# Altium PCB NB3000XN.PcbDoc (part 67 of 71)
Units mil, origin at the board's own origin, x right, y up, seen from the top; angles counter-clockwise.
Board outline 9527.56 x 6929.77 mil, 6 copper layers (Top Layer, GND+SHIELD, MidLayer1, MidLayer2, P2 - 3V3+5V0, Bottom Layer), stack 62.375 mil thick; 832 components, 1027 nets, 4655 pads, 4981 vias.
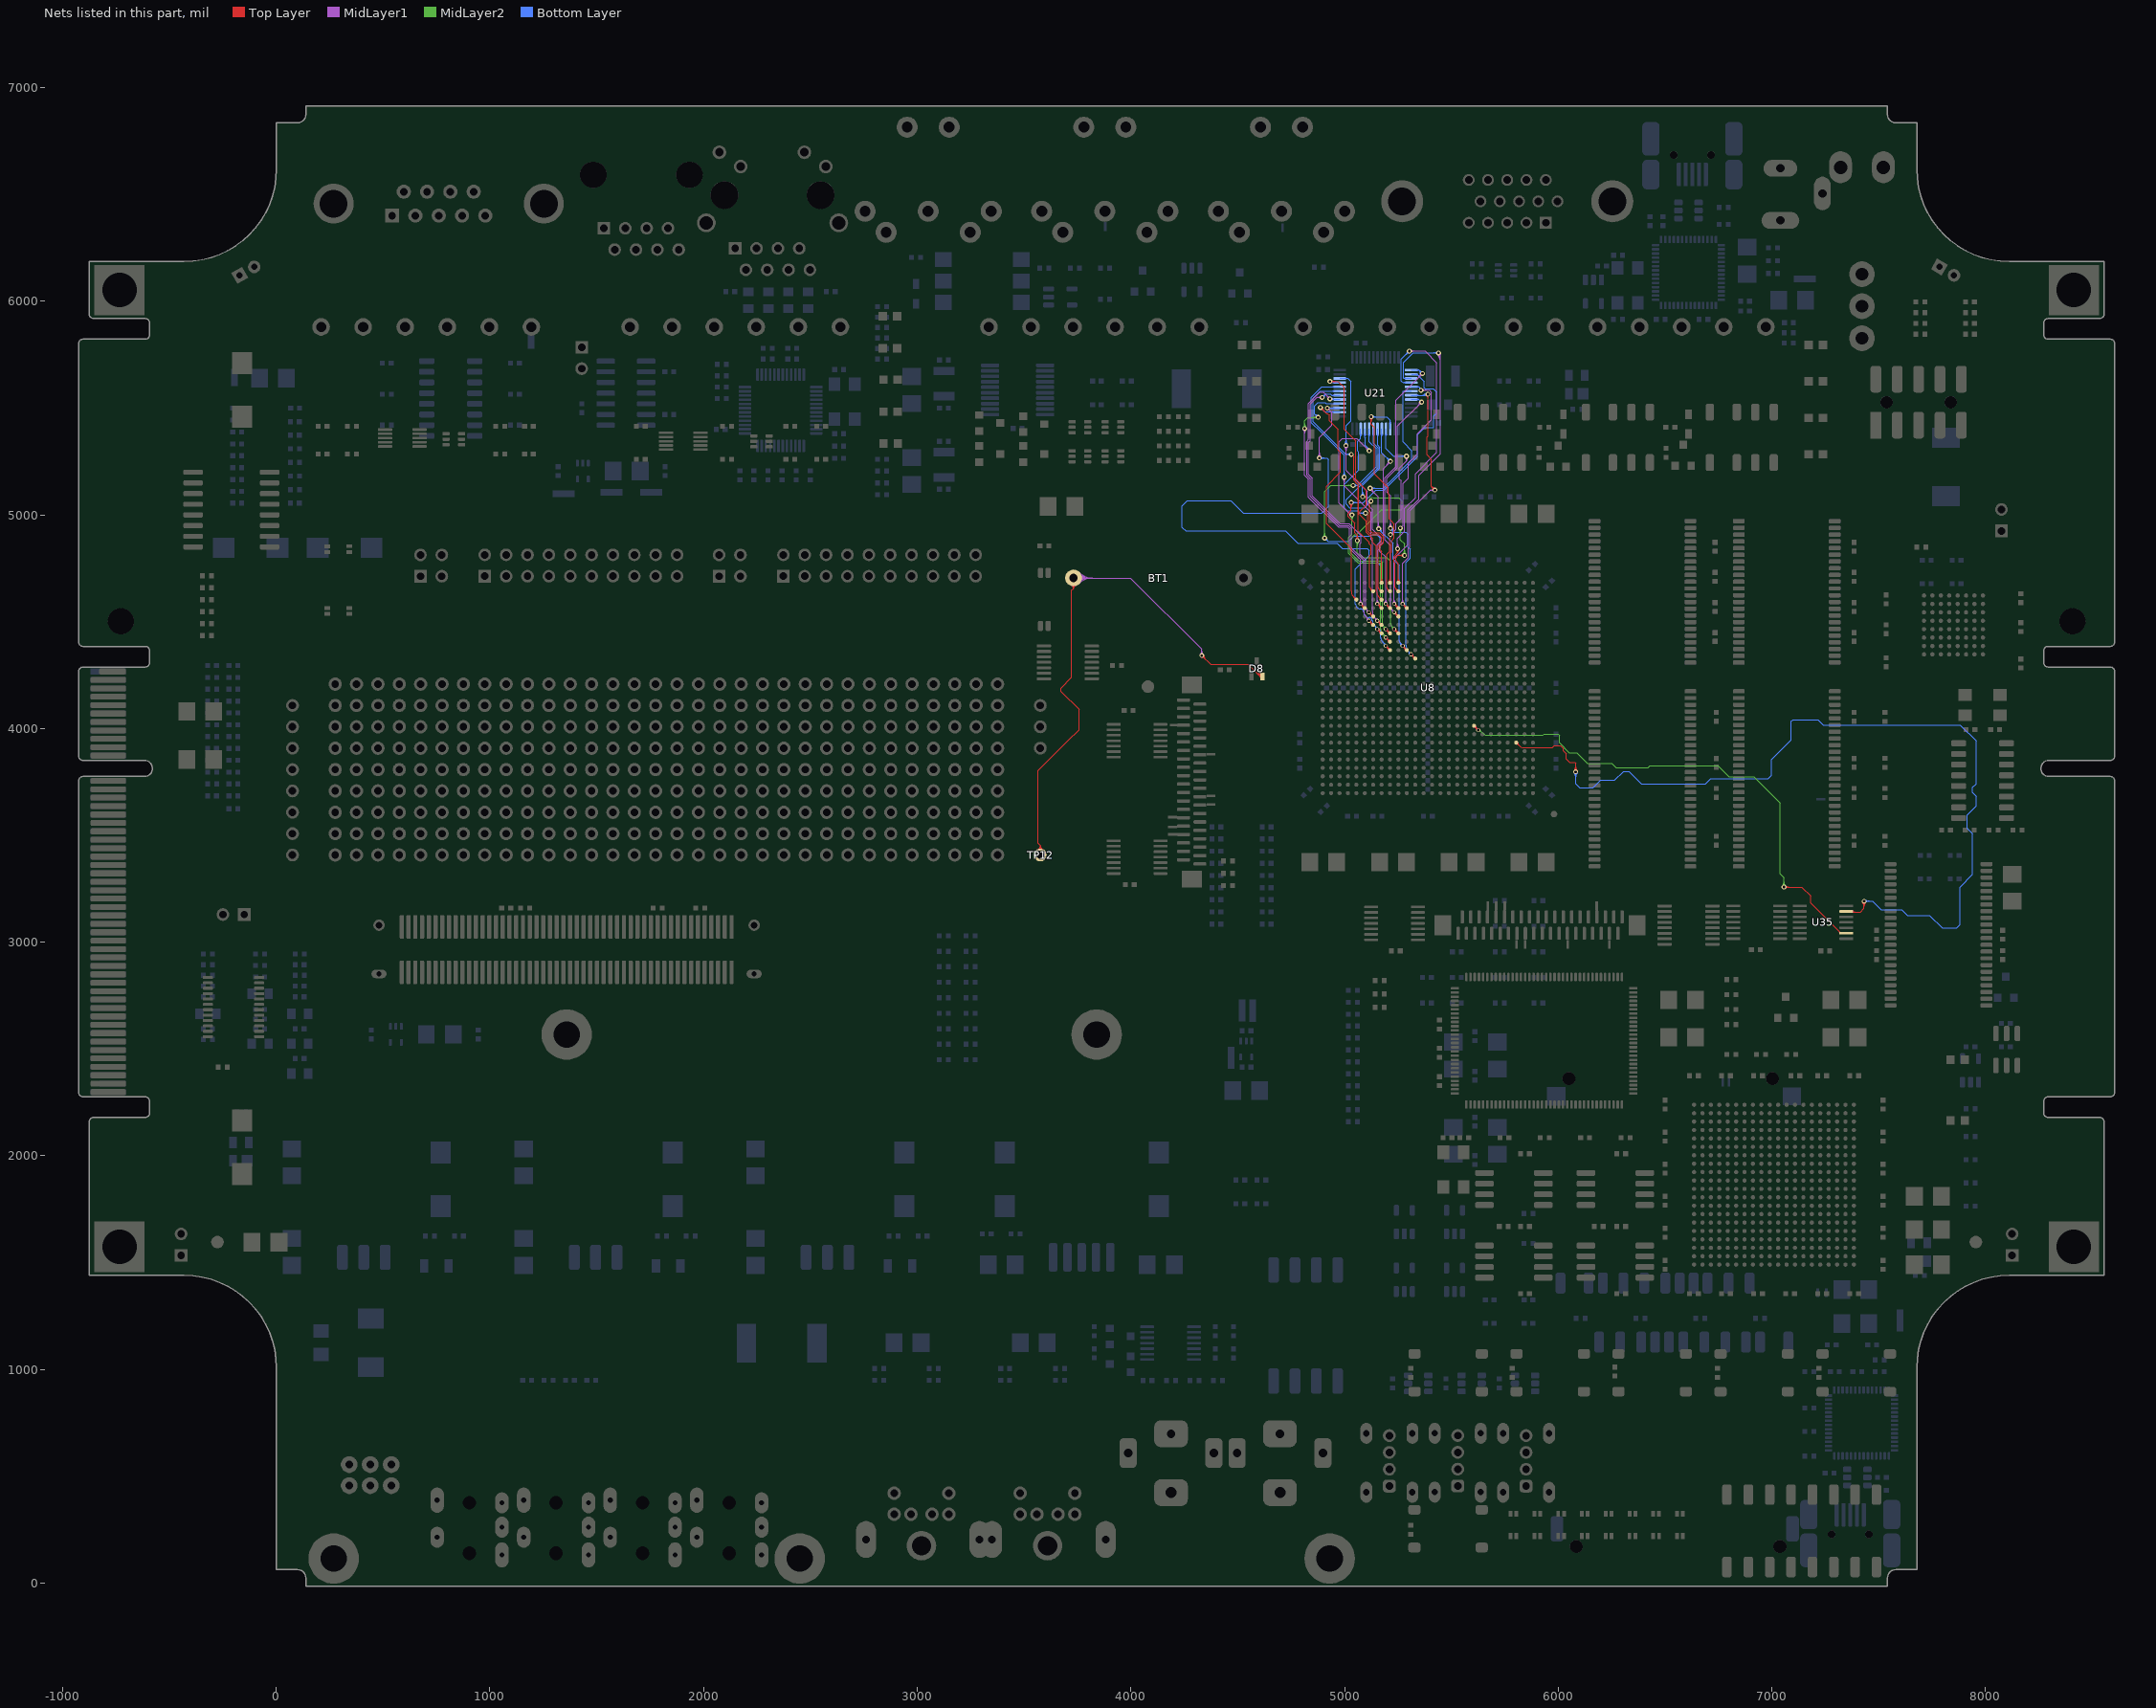
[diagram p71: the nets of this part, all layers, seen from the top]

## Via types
v1: diameter 23, hole 11.81, Top Layer to Bottom Layer, 3672 vias
v2: diameter 26, hole 11.81, Top Layer to Bottom Layer, 461 vias
v3: diameter 19, hole 11.81, Top Layer to Bottom Layer, tented both sides, 396 vias
v4: diameter 23.62, hole 11.81, Top Layer to Bottom Layer, 288 vias
v5: diameter 20, hole 11.81, Top Layer to Bottom Layer, 91 vias
v6: diameter 23, hole 11.81, Top Layer to Bottom Layer, tented both sides, 50 vias
v7: diameter 31, hole 11.81, Top Layer to Bottom Layer, 15 vias
v8: diameter 27.56, hole 11.81, Top Layer to Bottom Layer, tented both sides, 4 vias
v9: diameter 29, hole 11.81, Top Layer to Bottom Layer, 3 vias
v10: diameter 21, hole 11.81, Top Layer to Bottom Layer, 1 vias

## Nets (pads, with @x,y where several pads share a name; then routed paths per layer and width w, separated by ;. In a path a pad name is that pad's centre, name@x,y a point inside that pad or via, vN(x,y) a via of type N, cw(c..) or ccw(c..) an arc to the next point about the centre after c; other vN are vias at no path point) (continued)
USER_LEDS.LED7.GREEN: U8.Y24 U35.13 | length 4556.9
  Top Layer w4: v1@6075.14,3804.09 ccw(c6058.92,3820.31) 6081.86,3820.31 ccw(c6104.79,3820.31) v1@6088.57,3804.09 ; v1@6077.97,3801.26 ccw(c6068.58,3810.65) 6081.86,3810.65 ccw(c6095.14,3810.65) v1@6085.75,3801.26 ; v1(6081.86,3797.37) 6081.86,3838.14 6078.79,3841.21 6054.63,3841.21 6037.5,3858.34 6037.5,3882.73 6024.02,3896.2 6024.02,3907.29 6012.16,3919.15 5981.46,3919.15 5972.54,3910.23 5920,3910.23 5910,3910.23 5843.27,3910.23 ; U35.13@7348.5,3141.71 7415.19,3141.71 7431.86,3158.37 v1(7431.86,3191.71) ; U35.13@7374.98,3144.41 ccw(c7381.51,3150.93) 7381.51,3141.71 ; U35.13@7377.81,3147.24 ccw(c7391.16,3160.59) 7391.16,3141.71 ; v1@7425.14,3184.99 cw(c7408.92,3168.77) 7431.86,3168.77 cw(c7454.79,3168.77) v1@7438.57,3184.99 ; v1@7427.97,3187.82 cw(c7418.58,3178.43) 7431.86,3178.43 cw(c7445.14,3178.43) v1@7435.75,3187.82 ; 5815.92,3921.56 ccw(c5843.27,3948.91) 5843.27,3910.23 ; 5815.92,3921.56 ccw(c5843.27,3948.91) 5843.27,3910.23 ; 5815.92,3921.56 ccw(c5803.39,3909.03) 5803.39,3926.75 cw(c5803.39,3909.03) 5815.92,3921.56 ; 5815.92,3921.56 cw(c5828.45,3934.09) 5810.73,3934.09 ccw(c5828.45,3934.09) 5815.92,3921.56
  Bottom Layer w4: v1@6075.14,3790.66 cw(c6058.92,3774.44) 6081.86,3774.44 cw(c6104.79,3774.44) v1@6088.57,3790.66 ; v1@6077.97,3793.49 cw(c6068.58,3784.1) 6081.86,3784.1 cw(c6095.14,3784.1) v1@6085.75,3793.49 ; v1(6081.86,3797.37) 6081.86,3741.96 6099.78,3724.04 6164.19,3724.04 6198.52,3758.37 6265.19,3758.37 6306.86,3800.04 6331.86,3800.04 6390.19,3741.71 6690.19,3741.71 6715.19,3766.71 6983.19,3766.71 6998.52,3782.04 6998.52,3855.39 7090.19,3947.06 7090.19,4033.37 7098.52,4041.71 7215,4041.71 7240,4016.71 7306.86,4016.71 7345,4016.71 7881.86,4016.71 7956.86,3941.71 7956.86,3741.71 7940.19,3725.04 7940.19,3700.04 7956.86,3683.37 7956.86,3638.04 7915.19,3596.37 7915.19,3533.37 7940.19,3508.37 7940.19,3316.71 7881.86,3258.37 7881.86,3083.37 7865.19,3066.71 7797.02,3066.71 7738.73,3125 7633.69,3125 7607.23,3151.46 7510.79,3151.46 ; v1(7431.86,3191.71) 7470.54,3191.71 7510.79,3151.46 ; v1@7435.75,3187.82 cw(c7445.14,3178.43) 7445.14,3191.71 cw(c7445.14,3204.99) v1@7435.75,3195.6 ; v1@7438.57,3184.99 cw(c7454.79,3168.77) 7454.79,3191.71 cw(c7454.79,3214.64) v1@7438.57,3198.43 ; 7479.3,3182.95 7510.79,3151.46
USER_LEDS.LED7.RED: U8.V19 U35.9 | length 2687.9
  Top Layer w4: U8.V19@5606.54,4005.33 cw(c5606.54,3987.23) 5619.34,4000.03 cw(c5632.14,4012.83) U8.V19@5614.04,4012.83 ; U8.V19@5606.54,4005.49 cw(c5606.54,3987.77) 5619.07,4000.3 cw(c5631.6,4012.83) U8.V19@5613.88,4012.83 ; U8.V19@5606.54,4012.83 v3(5626.22,3993.15) ; v1(7056.86,3258.37) 7140.19,3258.37 7181.52,3217.04 7181.52,3183.71 7323.52,3041.71 7348.5,3041.71 U35.9@7348.5,3042.05 ; v1@7060.75,3254.49 cw(c7070.14,3245.1) 7070.14,3258.37 cw(c7070.14,3271.65) v1@7060.75,3262.26 ; v1@7063.57,3251.66 cw(c7079.79,3235.44) 7079.79,3258.37 cw(c7079.79,3281.31) v1@7063.57,3265.09 ; 7314.37,3050.86 cw(c7305.56,3042.05) U35.9@7318.02,3042.05 ; 7317.18,3048.06 ccw(c7322.02,3052.9) U35.9@7322.02,3046.05 ; 5613.42,4005.95 cw(c5600.61,3993.15) 5618.72,3993.15 ccw(c5600.61,3993.15) 5613.42,4005.95 ; 5613.42,4005.95 ccw(c5626.22,4018.76) 5626.22,4000.65 cw(c5626.22,4018.76) 5613.42,4005.95
  MidLayer2 w4: v3@5627.52,3985.76 cw(c5630.67,3967.93) 5641.05,3982.76 ; v3@5633.61,3994.45 ccw(c5651.44,3997.6) 5641.05,3982.76 ; v1@7050.14,3265.09 ccw(c7033.92,3281.31) 7056.86,3281.31 ccw(c7079.79,3281.31) v1@7063.57,3265.09 ; v1@7052.97,3262.26 ccw(c7043.58,3271.65) 7056.86,3271.65 ccw(c7070.14,3271.65) v1@7060.75,3262.26 ; 7055,3305 7039.86,3320.14 ; v1(7056.86,3258.37) 7056.86,3303.14 7039.86,3320.14 ; 5641.05,3982.76 5649.63,3975.68 ccw(c5665.85,3993.06) 5665.85,3969.29 5689.1,3969.29 5763.22,3969.29 5782.64,3969.29 5910,3969.29 5920,3969.29 5929.29,3969.29 5935,3975 6000,3975 6006,3969 6006,3933 6052,3887 6087.69,3887 6137.13,3837.56 6249.68,3837.56 6270.52,3816.71 6420.54,3816.71 6428.88,3825.04 6748.52,3825.04 6798.52,3775.04 6915.19,3775.04 7039.86,3650.37 7039.86,3320.14
VBATT: BT1.1 D8.2 TP12.1 | length 3668
  Top Layer w4: TP12.1@3564.05,3433.5 ccw(c3554.92,3452.64) 3576.12,3452.64 ; TP12.1@3565.78,3429.89 ccw(c3557.95,3446.29) 3576.12,3446.29 ccw(c3594.3,3446.29) TP12.1@3586.46,3429.89 ; TP12.1@3567.5,3426.28 ccw(c3560.97,3439.95) 3576.12,3439.95 ccw(c3591.27,3439.95) TP12.1@3584.74,3426.28 ; TP12.1@3576.12,3408.23 3576.12,3452.64 ; TP12.1@3588.19,3433.5 cw(c3597.33,3452.64) 3576.12,3452.64 ; BT1.1@3721.44,4669.07 cw(c3717.53,4655.42) 3731.73,4655.42 ; BT1.1@3722.54,4672.92 cw(c3719.05,4660.73) 3731.73,4660.73 cw(c3744.41,4660.73) BT1.1@3740.92,4672.92 ; BT1.1@3731.73,4705 3731.73,4655.42 ; BT1.1@3742.02,4669.07 ccw(c3745.93,4655.42) 3731.73,4655.42 ; v1@4331.86,4332.21 cw(c4331.86,4309.27) 4348.07,4325.49 cw(c4364.29,4341.71) v1@4341.36,4341.71 ; v1@4331.86,4336.21 cw(c4331.86,4322.93) 4341.25,4332.32 cw(c4350.64,4341.71) v1@4337.36,4341.71 ; v1(4331.86,4341.71) 4373.52,4300.04 4548.52,4300.04 4604,4244.57 D8.2@4615.59,4244.57 ; 4568.97,4279.59 ccw(c4615.59,4326.21) D8.2@4615.59,4260.28 ; 4575.8,4272.77 ccw(c4615.59,4312.56) D8.2@4615.59,4256.28 ; 4582.63,4265.94 ccw(c4615.59,4298.9) D8.2@4615.59,4252.28 ; 4589.46,4259.11 ccw(c4615.59,4285.24) D8.2@4615.59,4248.28 ; 4596.28,4252.28 ccw(c4615.59,4271.59) D8.2@4615.59,4244.28 ; 4603.11,4245.45 ccw(c4615.59,4257.93) D8.2@4615.59,4240.28 ; D8.2@4608.11,4241.73 ccw(c4604,4240.17) 4604,4244.57 ccw(c4604,4248.97) D8.2@4608.11,4247.4 ; 3576.12,3452.64 3565.19,3463.57 3565.19,3803.02 3705.04,3942.87 3757.19,3995.02 3757.19,4089.37 3673.52,4173.04 3673.52,4189.71 3723.52,4239.71 3723.52,4647.21 3731.73,4655.42
  MidLayer1 w4: BT1.1@3731.73,4705 3998.69,4705 4331.86,4371.83 v1(4331.86,4341.71) ; BT1.1@3744.01,4692.72 cw(c3773.67,4663.07) 3773.67,4705 cw(c3773.67,4746.94) BT1.1@3744.01,4717.28 ; BT1.1@3746.84,4689.89 cw(c3783.32,4653.41) 3783.32,4705 cw(c3783.32,4756.59) BT1.1@3746.84,4720.11 ; BT1.1@3749.67,4687.06 cw(c3792.98,4643.75) 3792.98,4705 cw(c3792.98,4766.25) BT1.1@3749.67,4722.94 ; BT1.1@3752.5,4684.23 cw(c3802.64,4634.09) 3802.64,4705 cw(c3802.64,4775.91) BT1.1@3752.5,4725.77 ; BT1.1@3755.33,4681.4 cw(c3812.29,4624.44) 3812.29,4705 cw(c3812.3,4785.56) BT1.1@3755.33,4728.6 ; BT1.1@3758.16,4678.58 cw(c3821.95,4614.78) 3821.95,4705 cw(c3821.95,4795.22) BT1.1@3758.16,4731.42 ; v1@4325.14,4348.43 ccw(c4308.92,4364.64) 4331.86,4364.64 ccw(c4354.79,4364.64) v1@4338.57,4348.43 ; v1@4327.97,4345.6 ccw(c4318.58,4354.99) 4331.86,4354.99 ccw(c4345.14,4354.99) v1@4335.75,4345.6
VGA.BLUE0: U8.K12 U21.8 | length 1731.7
  Top Layer w4: v3(5311.26,4347.48) U8.K12@5330.94,4327.8 ; U8.K12@5323.44,4327.8 ccw(c5305.34,4327.8) 5318.14,4340.6 ccw(c5330.94,4353.4) U8.K12@5330.94,4335.3 ; U8.K12@5323.6,4327.8 ccw(c5305.88,4327.8) 5318.41,4340.33 ccw(c5330.94,4352.86) U8.K12@5330.94,4335.14 ; 5324.06,4334.68 cw(c5336.87,4347.48) 5318.76,4347.48 ccw(c5336.87,4347.48) 5324.06,4334.68 ; 5324.06,4334.68 ccw(c5311.26,4321.87) 5311.26,4339.98 cw(c5311.26,4321.87) 5324.06,4334.68
  MidLayer1 w4: v1@5208.47,4944.09 ccw(c5192.26,4960.31) 5215.19,4960.31 ccw(c5238.13,4960.31) v1@5221.91,4944.09 ; v1@5211.3,4941.26 ccw(c5201.91,4950.65) 5215.19,4950.65 ccw(c5228.47,4950.65) v1@5219.08,4941.26 ; v1(5215.19,4937.37) 5215.19,5049.94 5215.19,5089.81 5198.19,5106.81 5198.19,5171.69 5248.52,5222.02 5248.52,5415.52 v1(5361,5528) ; v1@5351.5,5528 cw(c5328.56,5528) 5344.78,5511.78 cw(c5361,5495.56) v1@5361,5518.5 ; v1@5355.5,5528 cw(c5342.22,5528) 5351.61,5518.61 cw(c5361,5509.22) v1@5361,5522.5
  Bottom Layer w4: v1@5215.19,4927.87 cw(c5215.19,4904.94) 5231.41,4921.16 cw(c5247.63,4937.37) v1@5224.69,4937.37 ; v1@5215.19,4931.87 cw(c5215.19,4918.6) 5224.58,4927.99 cw(c5233.97,4937.37) v1@5220.69,4937.37 ; v1(5215.19,4937.37) 5232.56,4920 5287.52,4920 5297.52,4910 5297.52,4850.04 5306.86,4840.71 5306.86,4797.02 5287.4,4777.56 5287.4,4724.74 5287.4,4720 5287.4,4710 5287.4,4503.9 5287.4,4484.48 5287.4,4410.36 5287.4,4390.86 ccw(c5329.13,4390.86) 5299.62,4361.35 ; v3@5303.79,4348.13 ccw(c5285.75,4349.71) 5299.62,4361.35 ; v3@5311.91,4354.95 cw(c5313.49,4372.99) 5299.62,4361.35 ; U21.8@5312.32,5540.47 5346.09,5540.47 5358.56,5528 v1(5361,5528) ; U21.8@5338.68,5537.64 cw(c5345.51,5530.82) 5345.51,5540.47 cw(c5345.51,5550.13) U21.8@5338.68,5543.3
VGA.BLUE1: U8.D11 U21.7 | length 1561.1
  Top Layer w4: v3(5271.89,4583.7) U8.D11@5291.57,4564.02 ; U8.D11@5284.07,4564.02 ccw(c5265.97,4564.02) 5278.77,4576.82 ccw(c5291.57,4589.62) U8.D11@5291.57,4571.52 ; U8.D11@5284.23,4564.02 ccw(c5266.51,4564.02) 5279.04,4576.55 ccw(c5291.57,4589.08) U8.D11@5291.57,4571.36 ; v1(5390,5565) 5387.48,5565 5381.86,5559.37 5383.12,5558.12 5390.19,5551.04 5390.19,5370.04 5385.52,5365.37 5385.52,5281.37 5406.86,5260.04 5406.86,5133.37 v1(5423.52,5116.71) ; v1@5414.02,5116.71 ccw(c5391.09,5116.71) 5407.31,5132.93 ccw(c5423.52,5149.14) v1@5423.52,5126.21 ; v1@5418.02,5116.71 ccw(c5404.75,5116.71) 5414.14,5126.1 ccw(c5423.52,5135.49) v1@5423.52,5122.21 ; 5284.69,4570.9 cw(c5297.5,4583.7) 5279.39,4583.7 ccw(c5297.5,4583.7) 5284.69,4570.9 ; 5284.69,4570.9 ccw(c5271.89,4558.09) 5271.89,4576.2 cw(c5271.89,4558.09) 5284.69,4570.9
  MidLayer1 w4: v3@5266.59,4589 ccw(c5253.78,4601.81) 5271.89,4601.81 ccw(c5290,4601.81) v3@5277.19,4589 ; v3@5266.7,4588.89 ccw(c5254.16,4601.43) 5271.89,4601.43 ccw(c5289.62,4601.43) v3@5277.08,4588.89 ; v3(5271.89,4583.7) 5271.89,4661.38 5271.89,4710 5271.89,4720 5271.89,4773.37 5298.52,4800 5298.52,4843.02 5305.52,4850.02 5305.52,5020.37 5401.86,5116.71 ; v1@5416.54,5110.27 ccw(c5401.86,5096.75) 5401.86,5116.71 ; v1@5416.54,5123.14 cw(c5401.86,5136.66) 5401.86,5116.71 ; v1@5419.48,5112.98 ccw(c5410.98,5105.15) 5410.98,5116.71 ccw(c5410.98,5128.26) v1@5419.48,5120.43 ; v1(5423.52,5116.71) 5401.86,5116.71
  Bottom Layer w4: U21.7@5312.32,5560.16 5348.52,5560.16 5349.31,5559.37 5384.37,5559.37 v1(5390,5565) ; U21.7@5338.68,5557.33 cw(c5345.51,5550.5) 5345.51,5560.16 cw(c5345.51,5569.82) U21.7@5338.68,5562.99 ; 5353.48,5559.37 ccw(c5353.48,5601.52) v1@5383.28,5571.72 ; 5363.14,5559.37 ccw(c5363.14,5591.86) v1@5386.11,5568.89 ; 5372.8,5559.37 ccw(c5372.8,5582.2) v1@5388.94,5566.06
VGA.BLUE2: U8.J11 U21.6 | length 1834.4
  Top Layer w4: v3(5271.89,4386.85) U8.J11@5291.57,4367.17 ; U8.J11@5284.07,4367.17 ccw(c5265.97,4367.17) 5278.77,4379.97 ccw(c5291.57,4392.77) U8.J11@5291.57,4374.67 ; U8.J11@5284.23,4367.17 ccw(c5266.51,4367.17) 5279.04,4379.7 ccw(c5291.57,4392.23) U8.J11@5291.57,4374.51 ; 5284.69,4374.05 cw(c5297.5,4386.85) 5279.39,4386.85 ccw(c5297.5,4386.85) 5284.69,4374.05 ; 5284.69,4374.05 ccw(c5271.89,4361.24) 5271.89,4379.35 cw(c5271.89,4361.24) 5284.69,4374.05
  MidLayer1 w4: v1@5116.19,5125.04 v1@5116.23,5125 ; v1@5120,5115.5 cw(c5120,5101.66) 5129.78,5111.45 ; v1(5120,5125) v1@5116.23,5125 ; v1@5125.5,5125 ccw(c5147.88,5125) 5132.05,5109.18 ; v1@5129.5,5125 ccw(c5161.53,5125) 5138.88,5102.35 ; v1@5153.28,4941.72 ccw(c5144.65,4950.35) 5156.86,4950.35 ; 5156.86,4946.21 ccw(c5171.21,4946.21) v1@5161.06,4936.06 ; 5156.86,4955.87 ccw(c5180.87,4955.87) v1@5163.89,4938.89 ; 5156.86,4965.52 ccw(c5190.52,4965.52) v1@5166.72,4941.72 ; v1(5160,4935) 5158.9,4935 5156.86,4937.04 5156.86,5084.37 5118.12,5123.12 v1@5116.23,5125
  Bottom Layer w4: v1(5120,5125) 5116.23,5125 5116.19,5125.04 5181.88,5125.04 5315.19,5258.35 5315.19,5300.04 5273.52,5341.71 5273.52,5578.52 5274.84,5579.84 U21.6@5312.32,5579.84 ; v1@5123.89,5121.11 cw(c5133.38,5111.62) 5133.38,5125.04 ; v1@5123.89,5128.89 ccw(c5133.18,5138.18) 5133.18,5125.04 ; v1@5126.72,5118.28 cw(c5143.03,5101.97) 5143.03,5125.04 ; v1@5126.72,5131.72 ccw(c5142.84,5147.84) 5142.84,5125.04 ; v1@5160,4925.5 cw(c5160,4905.23) 5174.34,4919.56 ; v1(5160,4935) 5158.9,4935 5227.19,4866.71 5227.19,4792.81 5256.38,4763.62 5256.38,4757.96 5256.38,4720 5256.38,4710 5256.38,4503.9 5256.38,4410.36 ccw(c5270.43,4410.36) 5260.5,4400.43 ; v1@5165.5,4935 ccw(c5181.44,4935) 5170.17,4923.73 ; v1@5169.5,4935 ccw(c5195.1,4935) 5177,4916.9 ; v3@5264.42,4387.5 ccw(c5246.38,4389.08) 5260.25,4400.72 ccw(c5274.12,4412.36) v3@5272.54,4394.32 ; U21.6@5285.97,5577.01 ccw(c5279.14,5570.19) 5279.14,5579.84 ccw(c5279.14,5589.5) U21.6@5285.97,5582.67
VGA.BLUE3: U8.A10 U21.5 | length 1455.2
  Top Layer w4: U8.A10@5246.9,4687.43 ccw(c5234.1,4700.23) 5252.2,4700.23 ccw(c5270.31,4700.23) U8.A10@5257.51,4687.43 ; U8.A10@5252.2,4682.13 5252.2,4710 5252.2,4720 5252.2,4724.74 5252.21,4771.94 5240,4784.15 5240,4800 5250.37,4810.37 v1(5280.52,4810.37) ; v1@5273.81,4803.66 ccw(c5257.59,4787.44) 5257.59,4810.37 ccw(c5257.59,4833.31) v1@5273.81,4817.09 ; v1@5276.64,4806.49 ccw(c5267.25,4797.1) 5267.25,4810.37 ccw(c5267.25,4823.65) v1@5276.64,4814.26 ; 5252.2,4699.85 cw(c5234.48,4699.85) 5247.01,4687.32 ccw(c5234.48,4699.85) 5252.2,4699.85 ; 5252.2,4699.85 ccw(c5269.93,4699.85) 5257.4,4687.32 cw(c5269.93,4699.85) 5252.2,4699.85
  MidLayer1 w4: v1(5261.52,4938.37) 5273.52,4950.37 5273.52,5146.37 5298.52,5171.37 5298.52,5241.69 5309.11,5252.28 5342.19,5285.37 5342.19,5380.71 5407.5,5446.02 5407.5,5572.25 5396.37,5583.37 v1(5357.86,5583.37) ; v1@5361.75,5579.49 cw(c5371.14,5570.1) 5371.14,5583.37 cw(c5371.14,5596.65) v1@5361.75,5587.26 ; v1@5364.57,5576.66 cw(c5380.79,5560.44) 5380.79,5583.37 cw(c5380.79,5606.31) v1@5364.57,5590.09
  MidLayer2 w4: v1@5254.81,4931.66 cw(c5238.59,4915.44) 5261.52,4915.44 cw(c5284.46,4915.44) v1@5268.24,4931.66 ; v1@5257.64,4934.49 cw(c5248.25,4925.1) 5261.52,4925.1 cw(c5274.8,4925.1) v1@5265.41,4934.49 ; v1(5261.52,4938.37) 5261.52,4883.37 5280.52,4864.37 v1(5280.52,4810.37) ; v1@5273.81,4817.09 ccw(c5257.59,4833.31) 5280.52,4833.31 ccw(c5303.46,4833.31) v1@5287.24,4817.09 ; v1@5276.64,4814.26 ccw(c5267.25,4823.65) 5280.52,4823.65 ccw(c5293.8,4823.65) v1@5284.41,4814.26
  Bottom Layer w4: U21.5@5312.32,5599.53 5347.86,5599.53 5357.86,5589.53 v1(5357.86,5583.37) ; U21.5@5338.68,5596.7 cw(c5345.51,5589.87) 5345.51,5599.53 cw(c5345.51,5609.18) U21.5@5338.68,5602.36 ; 5349.45,5597.94 cw(c5340.38,5588.87) v1@5352.61,5585.03 ; 5352.14,5595.24 ccw(c5357.86,5600.96) v1@5357.86,5592.87
VGA.BLUE4: U8.B10 U21.4 | length 1775.1
  Top Layer w4: v1@5242.72,4833.85 cw(c5233.6,4822.04) 5248.52,4822.04 ; v1(5248.52,4841.37) 5248.52,4822.04 ; v1@5254.33,4833.85 ccw(c5263.45,4822.04) 5248.52,4822.04 ; 5236.7,4662.47 ccw(c5246.85,4662.47) 5239.67,4655.29 ; 5236.7,4662.47 ccw(c5246.85,4662.47) 5239.67,4655.29 ; 5236.7,4662.47 5236.7,4710 5236.7,4720 5236.7,4724.74 5236.7,4776.14 5232,4780.84 5232,4805.52 5248.52,4822.04 ; 5239.67,4655.29 ccw(c5252.2,4667.83) 5252.2,4650.1 cw(c5252.2,4667.83) 5239.67,4655.29 ; 5239.67,4655.29 cw(c5227.14,4642.76) 5244.86,4642.76 ccw(c5227.14,4642.76) 5239.67,4655.29
  MidLayer1 w4: v1@5241.81,4848.09 ccw(c5225.59,4864.31) 5248.52,4864.31 ccw(c5271.46,4864.31) v1@5255.24,4848.09 ; v1@5244.64,4845.26 ccw(c5235.25,4854.65) 5248.52,4854.65 ccw(c5261.8,4854.65) v1@5252.41,4845.26 ; v1(5248.52,4841.37) 5248.52,4890.37 5281.52,4923.37 5281.52,5030.32 5331.86,5080.65 5331.86,5191.71 5432.19,5292.04 5432.19,5711.69 ; v1(5303.52,5766.71) 5377.17,5766.71 5431.86,5712.02 ; v1@5307.41,5762.82 cw(c5316.8,5753.43) 5316.8,5766.71 cw(c5316.8,5779.99) v1@5307.41,5770.6 ; v1@5310.24,5759.99 cw(c5326.46,5743.77) 5326.46,5766.71 cw(c5326.46,5789.64) v1@5310.24,5773.43
  Bottom Layer w4: U21.4@5285.97,5616.38 ccw(c5279.14,5609.56) 5279.14,5619.21 ccw(c5279.14,5628.87) U21.4@5285.97,5622.04 ; v1@5294.02,5766.71 cw(c5271.09,5766.71) 5287.31,5750.49 cw(c5303.52,5734.27) v1@5303.52,5757.21 ; v1@5298.02,5766.71 cw(c5284.75,5766.71) 5294.14,5757.32 cw(c5303.52,5747.93) v1@5303.52,5761.21 ; v1(5303.52,5766.71) 5265.52,5728.71 5265.52,5627.21 5273.52,5619.21 U21.4@5312.32,5619.21
VGA.BLUE5: U8.D10 U21.3 | length 1972.9
  Top Layer w4: v3(5232.52,4583.7) U8.D10@5252.2,4564.02 ; U8.D10@5244.7,4564.02 ccw(c5226.6,4564.02) 5239.4,4576.82 ccw(c5252.2,4589.62) U8.D10@5252.2,4571.52 ; U8.D10@5244.86,4564.02 ccw(c5227.14,4564.02) 5239.67,4576.55 ccw(c5252.2,4589.08) U8.D10@5252.2,4571.36 ; 5245.32,4570.9 cw(c5258.13,4583.7) 5240.02,4583.7 ccw(c5258.13,4583.7) 5245.32,4570.9 ; 5245.32,4570.9 ccw(c5232.52,4558.09) 5232.52,4576.2 cw(c5232.52,4558.09) 5245.32,4570.9
  MidLayer1 w4: v3@5227.33,4588.89 ccw(c5214.79,4601.43) 5232.52,4601.43 ccw(c5250.25,4601.43) v3@5237.71,4588.89 ; v3(5232.52,4583.7) 5232.52,4661.38 5232.52,4710 5232.52,4720 5232.52,4724.74 5232.52,4795.37 5297.52,4860.37 5297.52,5023.69 5348.19,5074.35 5348.19,5185.41 5448.52,5285.75 5448.52,5750.04 v1(5440.19,5758.37) ; v1@5433.47,5751.66 cw(c5397.14,5715.32) 5448.52,5715.32 ; v1@5436.3,5754.49 cw(c5406.79,5724.98) 5448.52,5724.98 ; v1@5439.13,5757.31 cw(c5416.45,5734.63) 5448.52,5734.63 ; v1@5441.96,5760.14 cw(c5426.11,5744.29) 5448.52,5744.29 ; 5232.52,4601.81 cw(c5214.41,4601.81) 5227.22,4589 ccw(c5214.41,4601.81) 5232.52,4601.81 ; 5232.52,4601.81 ccw(c5250.63,4601.81) 5237.82,4589 cw(c5250.63,4601.81) 5232.52,4601.81
  Bottom Layer w4: U21.3@5285.97,5636.07 ccw(c5279.14,5629.24) 5279.14,5638.9 ccw(c5279.14,5648.55) U21.3@5285.97,5641.73 ; U21.3@5312.32,5638.9 5278.52,5638.9 5276.52,5640.9 5276.52,5713.71 5321.19,5758.37 v1(5440.19,5758.37) ; v1@5433.47,5751.66 ccw(c5417.26,5735.44) 5417.26,5758.37 ccw(c5417.26,5781.31) v1@5433.47,5765.09 ; v1@5436.3,5754.49 ccw(c5426.91,5745.1) 5426.91,5758.37 ccw(c5426.91,5771.65) v1@5436.3,5762.26
VGA.BLUE6: U8.G10 U21.2 | length 2168.7
  Top Layer w4: v1@5024.47,5051.66 cw(c5008.26,5035.44) 5031.19,5035.44 cw(c5054.13,5035.44) v1@5037.91,5051.66 ; v1@5027.3,5054.49 cw(c5017.91,5045.1) 5031.19,5045.1 cw(c5044.47,5045.1) v1@5035.08,5054.49 ; v1@5031.86,5058.37 v1(5031.19,5058.37) 5031.19,5020.94 5017.5,5007.25 5017.5,4992.75 5048.52,4961.73 5048.52,4916.41 5060,4904.94 v1(5060,4880) 5060,4878.18 5056.86,4875.04 v1@5055.95,4875.95 ; v1@5053.28,4886.72 ccw(c5037.06,4902.93) 5060,4902.93 ccw(c5082.93,4902.93) v1@5066.72,4886.72 ; v1@5056.11,4883.89 ccw(c5046.72,4893.28) 5060,4893.28 ccw(c5073.28,4893.28) v1@5063.89,4883.89 ; v3(5232.52,4465.59) U8.G10@5252.2,4445.91 ; U8.G10@5244.7,4445.91 ccw(c5226.6,4445.91) 5239.4,4458.71 ccw(c5252.2,4471.51) U8.G10@5252.2,4453.41 ; U8.G10@5244.86,4445.91 ccw(c5227.14,4445.91) 5239.67,4458.44 ccw(c5252.2,4470.97) U8.G10@5252.2,4453.25 ; 5245.32,4452.79 cw(c5258.13,4465.59) 5240.02,4465.59 ccw(c5258.13,4465.59) 5245.32,4452.79 ; 5245.32,4452.79 ccw(c5232.52,4439.98) 5232.52,4458.09 cw(c5232.52,4439.98) 5245.32,4452.79
  MidLayer2 w4: v1@5053.28,4873.28 cw(c5037.06,4857.06) 5060,4857.06 cw(c5082.93,4857.06) v1@5066.72,4873.28 ; v1@5056.11,4876.11 cw(c5046.72,4866.72) 5060,4866.72 cw(c5073.28,4866.72) v1@5063.89,4876.11 ; v1(5060,4880) 5060,4821.9 5081.86,4800.04 5198.52,4800.04 5217.02,4781.55 5217.02,4728.73 5217.01,4724.74 5217.01,4720 5217.01,4710 5217.01,4640.9 ; 5217.01,4503.03 5217.01,4489.1 ; 5217.01,4699.16 5217.01,4640.9 ; 5221.13,4479.17 cw(c5231.06,4489.1) 5217.01,4489.1 ; v3@5225.05,4466.24 ccw(c5207.01,4467.82) 5220.88,4479.46 ccw(c5234.75,4491.1) v3@5233.17,4473.06 ; 5217.01,4489.1 5217.01,4582.64 5217.01,4640.9
  Bottom Layer w4: v1(5031.19,5058.37) 5089.19,5058.37 5147.52,5116.71 5184.86,5116.71 5341.52,5273.37 5341.52,5375.04 5374.86,5408.37 5415.52,5408.37 5417.19,5410.04 5417.19,5462.04 5431.86,5476.71 5431.86,5575.04 5415.19,5591.71 5376.86,5591.71 5373.52,5595.04 5373.52,5625.04 5340.19,5658.37 U21.2@5315.19,5658.37 ; v1@5035.08,5054.49 cw(c5044.47,5045.1) 5044.47,5058.37 cw(c5044.47,5071.65) v1@5035.08,5062.26 ; v1@5037.91,5051.66 cw(c5054.13,5035.44) 5054.13,5058.37 cw(c5054.13,5081.31) v1@5037.91,5065.09 ; U21.2@5335.85,5654.58 cw(c5335.85,5634.95) 5349.73,5648.83 ; U21.2@5335.85,5658.58 cw(c5335.85,5648.61) 5342.9,5655.66
VGA.BLUE7: U8.E10 U21.1 | length 1560.7
  Top Layer w4: v3(5232.52,4544.33) U8.E10@5252.2,4524.65 ; U8.E10@5244.7,4524.65 ccw(c5226.6,4524.65) 5239.4,4537.45 ccw(c5252.2,4550.25) U8.E10@5252.2,4532.15 ; U8.E10@5244.86,4524.65 ccw(c5227.14,4524.65) 5239.67,4537.18 ccw(c5252.2,4549.71) U8.E10@5252.2,4531.99 ; 5245.32,4531.53 cw(c5258.13,4544.33) 5240.02,4544.33 ccw(c5258.13,4544.33) 5245.32,4531.53 ; 5245.32,4531.53 ccw(c5232.52,4518.72) 5232.52,4536.83 cw(c5232.52,4518.72) 5245.32,4531.53
  MidLayer1 w4: 5217.01,4581.77 5217.01,4567.84 ; 5221.13,4557.91 cw(c5231.06,4567.84) 5217.01,4567.84 ; v3@5225.05,4544.98 ccw(c5207.01,4546.56) 5220.88,4558.2 ccw(c5234.75,4569.84) v3@5233.17,4551.8 ; v1@5355.69,5662.04 cw(c5332.76,5662.04) 5348.97,5645.82 cw(c5365.19,5629.61) v1@5365.19,5652.54 ; v1@5359.69,5662.04 cw(c5346.41,5662.04) 5355.8,5652.65 cw(c5365.19,5643.26) v1@5365.19,5656.54 ; v1(5365.19,5662.04) 5240.19,5537.04 5240.19,5225 5190.19,5175 5190.19,4883.37 5217.01,4856.55 5217.01,4724.74 5217.01,4720 5217.01,4710 5217.01,4661.38 5217.01,4567.84
  Bottom Layer w4: U21.1@5312.32,5678.27 5348.96,5678.27 ; U21.1@5338.68,5675.44 cw(c5345.51,5668.61) 5345.51,5678.27 cw(c5345.51,5687.92) U21.1@5338.68,5681.1 ; v1@5355.69,5662.04 ccw(c5332.76,5662.04) 5348.97,5678.26 ; v1@5359.69,5662.04 ccw(c5346.41,5662.04) 5355.8,5671.43 ccw(c5365.19,5680.82) v1@5365.19,5667.54 ; v1(5365.19,5662.04) 5348.96,5678.27 ; v1@5365.19,5671.54 cw(c5365.19,5694.48) 5348.97,5678.26
VGA.GREEN0: U8.D8 U21.34 | length 1511.7
  Top Layer w4: v3(5153.78,4583.7) U8.D8@5173.46,4564.02 ; U8.D8@5165.96,4564.02 ccw(c5147.86,4564.02) 5160.66,4576.82 ccw(c5173.46,4589.62) U8.D8@5173.46,4571.52 ; U8.D8@5166.12,4564.02 ccw(c5148.4,4564.02) 5160.93,4576.55 ccw(c5173.46,4589.08) U8.D8@5173.46,4571.36 ; 5166.58,4570.9 cw(c5179.39,4583.7) 5161.28,4583.7 ccw(c5179.39,4583.7) 5166.58,4570.9 ; 5166.58,4570.9 ccw(c5153.78,4558.09) 5153.78,4576.2 cw(c5153.78,4558.09) 5166.58,4570.9
  MidLayer1 w4: v1@5000.14,5318.32 cw(c4983.92,5302.11) 5006.86,5302.11 cw(c5029.79,5302.11) v1@5013.57,5318.32 ; v1@5002.97,5321.15 cw(c4993.58,5311.76) 5006.86,5311.76 cw(c5020.14,5311.76) v1@5010.75,5321.15 ; v1(5006.86,5325.04) 5006.86,5208.37 5105.52,5109.71 5105.52,5051.37 5131.86,5025.04 5131.86,4933.37 5173.52,4891.71 5173.52,4879.79 5153.78,4860.04 5153.78,4724.74 5153.78,4720 5153.78,4710 5153.78,4661.38 v3(5153.78,4583.7) ; v3@5148.48,4589 ccw(c5135.67,4601.81) 5153.78,4601.81 ccw(c5171.89,4601.81) v3@5159.08,4589 ; v3@5148.59,4588.89 ccw(c5136.05,4601.43) 5153.78,4601.43 ccw(c5171.51,4601.43) v3@5158.97,4588.89
  Bottom Layer w4: U21.34@4977.68,5638.9 5015.52,5638.9 5029.52,5624.9 5029.52,5441.37 5006.86,5418.71 v1(5006.86,5325.04) ; v1@5000.14,5331.76 ccw(c4983.92,5347.98) 5006.86,5347.98 ccw(c5029.79,5347.98) v1@5013.57,5331.76 ; v1@5002.97,5328.93 ccw(c4993.58,5338.32) 5006.86,5338.32 ccw(c5020.14,5338.32) v1@5010.75,5328.93 ; U21.34@5004.03,5636.07 cw(c5010.86,5629.24) 5010.86,5638.9 cw(c5010.86,5648.55) U21.34@5004.03,5641.73
VGA.GREEN1: U8.C8 U21.33 | length 1441
  Top Layer w4: v1(4931.86,5625.04) 4970.86,5625.04 4998.52,5597.37 4998.52,5400.04 5052.19,5346.37 5052.19,5166.71 ; v1@4935.75,5621.15 cw(c4945.14,5611.76) 4945.14,5625.04 cw(c4945.14,5638.32) v1@4935.75,5628.93 ; v1@4938.57,5618.32 cw(c4954.79,5602.11) 4954.79,5625.04 cw(c4954.79,5647.98) v1@4938.57,5631.76 ; U8.C8@5166.12,4603.39 ccw(c5148.4,4603.39) 5160.93,4615.92 ; U8.C8@5173.46,4610.73 cw(c5173.46,4628.45) 5160.93,4615.92 ; 5052.19,5166.71 5098.52,5120.37 ; 5052.19,5166.71 5098.52,5120.37 ; 5098.52,5120.37 5102.5,5116.4 5102.5,5045.68 5073.52,5016.71 5073.52,4998.71 5101.19,4971.04 5101.19,4919.71 5131.86,4889.04 5131.86,4870.96 5149.6,4853.22 5149.6,4720 5149.6,4710 5149.6,4643.27 ccw(c5188.28,4643.27) 5160.93,4615.92
  Bottom Layer w4: v1(4931.86,5625.04) 4937.69,5619.21 U21.33@4977.68,5619.21 ; v1@4932.92,5626.1 ccw(c4949.55,5642.73) U21.33@4949.55,5619.21 ; v1@4935.75,5628.93 ccw(c4959.21,5652.39) U21.33@4959.21,5619.21 ; v1@4938.57,5631.76 ccw(c4968.86,5662.05) U21.33@4968.86,5619.21 ; U21.33@4951.32,5616.38 ccw(c4944.49,5609.56) 4944.49,5619.21 ccw(c4944.49,5628.87) U21.33@4951.32,5622.04
VGA.GREEN2: U8.F8 U21.32 | length 1618
  Top Layer w4: v3(5153.78,4504.96) U8.F8@5173.46,4485.28 ; U8.F8@5165.96,4485.28 ccw(c5147.86,4485.28) 5160.66,4498.08 ccw(c5173.46,4510.88) U8.F8@5173.46,4492.78 ; U8.F8@5166.12,4485.28 ccw(c5148.4,4485.28) 5160.93,4497.81 ccw(c5173.46,4510.34) U8.F8@5173.46,4492.62 ; 5166.58,4492.16 cw(c5179.39,4504.96) 5161.28,4504.96 ccw(c5179.39,4504.96) 5166.58,4492.16 ; 5166.58,4492.16 ccw(c5153.78,4479.35) 5153.78,4497.46 cw(c5153.78,4479.35) 5166.58,4492.16
  MidLayer1 w4: v1@4991.81,5169.99 cw(c4975.59,5153.77) 4998.52,5153.77 cw(c5021.46,5153.77) v1@5005.24,5169.99 ; v1@4994.64,5172.82 cw(c4985.25,5163.43) 4998.52,5163.43 cw(c5011.8,5163.43) v1@5002.41,5172.82 ; v1(4998.52,5176.71) 4998.52,5136.04 5123.52,5011.04 5123.52,4885.77 5129.92,4879.37 5129.92,4720 5129.92,4710 5129.92,4661.38 5129.92,4641.96 5129.92,4567.84 ; 5129.92,4581.77 5129.92,4567.84 ; v3@5146.31,4505.61 ccw(c5128.27,4507.19) 5142.14,4518.83 ; v3@5154.43,4512.43 cw(c5156.01,4530.47) 5142.14,4518.83 ; 5129.92,4567.84 5129.92,4548.34 ccw(c5171.65,4548.34) 5142.14,4518.83
  Bottom Layer w4: U21.32@4951.32,5596.7 ccw(c4944.49,5589.87) 4944.49,5599.53 ccw(c4944.49,5609.18) U21.32@4951.32,5602.36 ; U21.32@4977.68,5599.53 4894.53,5599.53 4845,5550 4845,5432.23 4886.15,5391.09 4998.52,5278.71 v1(4998.52,5176.71) ; v1@4991.81,5183.43 ccw(c4975.59,5199.64) 4998.52,5199.64 ccw(c5021.46,5199.64) v1@5005.24,5183.43 ; v1@4994.64,5180.6 ccw(c4985.25,5189.99) 4998.52,5189.99 ccw(c5011.8,5189.99) v1@5002.41,5180.6
VGA.GREEN3: U8.B7 U21.31 | length 1562.5
  Top Layer w4: v1(5031.86,5283.37) 5042.81,5272.42 5042.81,5162.42 5057.86,5147.37 ; 5055.83,5149.4 5064.7,5140.54 ; 5065.19,5001.69 5065.19,5140.04 5064.7,5140.54 ; 5064.7,4960 5064.7,4922.87 5115.19,4872.37 5115.19,4865 5123.52,4856.67 5123.52,4830 5123.52,4816.64 5118.59,4811.7 5118.59,4737.37 5118.59,4733 5118.59,4724.74 5118.59,4720 5118.59,4710 5118.59,4662.47 ; 5064.7,4960 5064.7,5001.19 5064.7,4960 ; 5064.7,4960 5064.7,5140.54 ; 5118.59,4662.47 ccw(c5128.74,4662.47) 5121.56,4655.29 ; 5118.59,4662.47 ccw(c5128.74,4662.47) 5121.56,4655.29 ; 5121.56,4655.29 ccw(c5134.09,4667.83) 5134.09,4650.1 cw(c5134.09,4667.83) 5121.56,4655.29 ; 5121.56,4655.29 cw(c5109.03,4642.76) 5126.75,4642.76 ccw(c5109.03,4642.76) 5121.56,4655.29
  Bottom Layer w4: 4856.86,5550.04 4886.66,5579.84 ; U21.31@4951.32,5577.01 ccw(c4944.49,5570.19) 4944.49,5579.84 ccw(c4944.49,5589.5) U21.31@4951.32,5582.67 ; U21.31@4977.68,5579.84 4886.66,5579.84 ; v1@5025.14,5276.66 ccw(c5008.92,5260.44) 5008.92,5283.37 ccw(c5008.92,5306.31) v1@5025.14,5290.09 ; v1@5027.97,5279.49 ccw(c5018.58,5270.1) 5018.58,5283.37 ccw(c5018.58,5296.65) v1@5027.97,5287.26 ; v1(5031.86,5283.37) 5005.17,5283.37 4853,5435.55 4853,5546.69 4886.16,5579.84 4886.66,5579.84
VGA.GREEN4: U8.E7 U21.30 | length 1563
  Top Layer w4: v3(5114.41,4544.33) U8.E7@5134.09,4524.65 ; U8.E7@5126.59,4524.65 ccw(c5108.49,4524.65) 5121.29,4537.45 ccw(c5134.09,4550.25) U8.E7@5134.09,4532.15 ; U8.E7@5126.75,4524.65 ccw(c5109.03,4524.65) 5121.56,4537.18 ccw(c5134.09,4549.71) U8.E7@5134.09,4531.99 ; 5127.21,4531.53 ccw(c5114.41,4518.72) 5114.41,4536.83 cw(c5114.41,4518.72) 5127.21,4531.53 ; 5127.21,4531.53 cw(c5140.02,4544.33) 5121.91,4544.33 ccw(c5140.02,4544.33) 5127.21,4531.53
  MidLayer1 w4: v1@4888.81,5543.32 ccw(c4872.59,5527.11) 4872.59,5550.04 ccw(c4872.59,5572.98) v1@4888.81,5556.76 ; v1@4891.64,5546.15 ccw(c4882.25,5536.76) 4882.25,5550.04 ccw(c4882.25,5563.32) v1@4891.64,5553.93 ; v1(4895.52,5550.04) 4871.84,5550.04 4840.19,5518.39 4840.19,5494.71 4840.19,5347.37 4831.86,5339.04 4831.86,5189.34 4848.52,5172.67 4848.52,5089.32 4978.8,4959.04 5021.82,4959.04 5077.86,4903 5077.86,4869.37 5073.52,4865.04 5073.52,4815.37 5098.9,4790 5098.9,4724.74 5098.9,4720 5098.9,4710 5098.9,4661.38 5098.9,4567.84 ccw(c5112.95,4567.84) 5103.02,4557.91 ; v3@5106.94,4544.98 ccw(c5088.9,4546.56) 5102.77,4558.2 ccw(c5116.64,4569.84) v3@5115.06,4551.8
  Bottom Layer w4: v1(4895.52,5550.04) 4912.19,5566.71 4934.97,5566.71 4941.52,5560.16 U21.30@4977.68,5560.16 ; v1@4895.52,5555.54 ccw(c4895.52,5568.82) 4904.91,5559.43 ccw(c4914.3,5550.04) v1@4901.02,5550.04 ; v1@4895.52,5559.54 ccw(c4895.52,5582.48) 4911.74,5566.26 ccw(c4927.96,5550.04) v1@4905.02,5550.04 ; U21.30@4951.32,5557.33 ccw(c4944.49,5550.5) 4944.49,5560.16 ccw(c4944.49,5569.82) U21.30@4951.32,5562.99
VGA.GREEN5: U8.F7 U21.29 | length 1637.1
  Top Layer w4: v3(5114.41,4504.96) U8.F7@5134.09,4485.28 ; U8.F7@5126.59,4485.28 ccw(c5108.49,4485.28) 5121.29,4498.08 ccw(c5134.09,4510.88) U8.F7@5134.09,4492.78 ; U8.F7@5126.75,4485.28 ccw(c5109.03,4485.28) 5121.56,4497.81 ccw(c5134.09,4510.34) U8.F7@5134.09,4492.62 ; 5127.21,4492.16 ccw(c5114.41,4479.35) 5114.41,4497.46 cw(c5114.41,4479.35) 5127.21,4492.16 ; 5127.21,4492.16 cw(c5140.02,4504.96) 5121.91,4504.96 ccw(c5140.02,4504.96) 5127.21,4492.16
  MidLayer1 w4: 4840,5115 4840,5086.53 4975.48,4951.04 5018.5,4951.04 5031.86,4937.69 5031.86,4845.73 5090.55,4787.04 5090.55,4724.74 5090.55,4720 5090.55,4710 5090.55,4661.38 5090.55,4641.96 5090.55,4567.84 ; 4840,5150 4840,5169.88 4823.52,5186.35 4823.52,5344.04 4831.86,5352.37 4831.86,5521.37 4885.52,5575.04 4899.86,5575.04 v1(4931.52,5543.37) ; 4840.19,5115 4840.19,5150 ; v1@4922.02,5543.37 ccw(c4899.09,5543.37) 4915.31,5559.59 ccw(c4931.52,5575.81) v1@4931.52,5552.87 ; v1@4926.02,5543.37 ccw(c4912.75,5543.37) 4922.13,5552.76 ccw(c4931.52,5562.15) v1@4931.52,5548.87 ; 5090.55,4581.77 5090.55,4567.84 ; v3@5107.02,4506.26 ccw(c5089.19,4509.41) 5104.02,4519.79 ; v3@5115.71,4512.35 cw(c5118.86,4530.18) 5104.02,4519.79 ; 5090.55,4567.84 5090.55,4544.59 ccw(c5114.32,4544.59) 5096.94,4528.37 5104.02,4519.79
  Bottom Layer w4: v1(4931.52,5543.37) 4934.43,5540.47 U21.29@4977.68,5540.47 ; v1@4935.41,5547.26 ccw(c4951.81,5563.66) U21.29@4951.81,5540.47 ; v1@4938.24,5536.66 cw(c4947.45,5527.45) 4947.45,5540.47 ; v1@4938.24,5550.09 ccw(c4961.47,5573.32) U21.29@4961.47,5540.47 ; U21.29@4951.32,5537.64 ccw(c4944.49,5530.82) 4944.49,5540.47 ccw(c4944.49,5550.13) U21.29@4951.32,5543.3
VGA.GREEN6: U8.D6 U21.28 | length 1698.3
  Top Layer w4: v3(5075.04,4583.7) U8.D6@5094.72,4564.02 ; U8.D6@5087.22,4564.02 ccw(c5069.12,4564.02) 5081.92,4576.82 ccw(c5094.72,4589.62) U8.D6@5094.72,4571.52 ; U8.D6@5087.38,4564.02 ccw(c5069.66,4564.02) 5082.19,4576.55 ccw(c5094.72,4589.08) U8.D6@5094.72,4571.36 ; 5087.84,4570.9 cw(c5100.65,4583.7) 5082.54,4583.7 ccw(c5100.65,4583.7) 5087.84,4570.9 ; 5087.84,4570.9 ccw(c5075.04,4558.09) 5075.04,4576.2 cw(c5075.04,4558.09) 5087.84,4570.9
  MidLayer1 w4: v1@4806.81,5397.66 cw(c4790.59,5381.44) 4813.52,5381.44 cw(c4836.46,5381.44) v1@4820.24,5397.66 ; v1@4809.64,5400.49 cw(c4800.25,5391.1) 4813.52,5391.1 cw(c4826.8,5391.1) v1@4817.41,5400.49 ; v1(4813.52,5404.37) 4813.52,5185.04 4831.86,5166.71 4831.86,5083.35 4972.17,4943.04 5015.19,4943.04 5023.52,4934.71 5023.52,4842.75 5075.04,4791.23 5075.04,4720 5075.04,4710 5075.04,4661.38 v3(5075.04,4583.7) ; v3@5069.85,4588.89 ccw(c5057.31,4601.43) 5075.04,4601.43 ccw(c5092.77,4601.43) v3@5080.23,4588.89 ; 5075.04,4601.81 cw(c5056.93,4601.81) 5069.74,4589 ccw(c5056.93,4601.81) 5075.04,4601.81 ; 5075.04,4601.81 ccw(c5093.15,4601.81) 5080.34,4589 cw(c5093.15,4601.81) 5075.04,4601.81
  MidLayer2 w4: v1@4806.81,5411.09 ccw(c4790.59,5427.31) 4813.52,5427.31 ccw(c4836.46,5427.31) v1@4820.24,5411.09 ; v1@4809.64,5408.26 ccw(c4800.25,5417.65) 4813.52,5417.65 ccw(c4826.8,5417.65) v1@4817.41,5408.26 ; v1(4813.52,5404.37) 4813.52,5441.67 4828.86,5457 v1(4877,5457) ; v1@4870.28,5450.28 ccw(c4854.06,5434.06) 4854.06,5457 ccw(c4854.06,5479.93) v1@4870.28,5463.72 ; v1@4873.11,5453.11 ccw(c4863.72,5443.72) 4863.72,5457 ccw(c4863.72,5470.28) v1@4873.11,5460.89
  Bottom Layer w4: v1@4867.5,5457.09 ccw(c4845.31,5457.31) 4861,5473 ccw(c4876.69,5488.69) v1@4876.91,5466.5 ; v1@4871.5,5457.05 ccw(c4858.65,5457.18) 4867.74,5466.26 ccw(c4876.82,5475.35) v1@4876.95,5462.5 ; v1(4877,5457) 4861,5473 4861,5511 4875,5525 4910,5525 4914.21,5520.79 U21.28@4977.68,5520.79
VGA.GREEN7: U8.G8 U21.27 | length 3183.3
  Top Layer w4: v3(5153.78,4465.59) U8.G8@5173.46,4445.91 ; U8.G8@5165.96,4445.91 ccw(c5147.86,4445.91) 5160.66,4458.71 ccw(c5173.46,4471.51) U8.G8@5173.46,4453.41 ; U8.G8@5166.12,4445.91 ccw(c5148.4,4445.91) 5160.93,4458.44 ccw(c5173.46,4470.97) U8.G8@5173.46,4453.25 ; 5166.58,4452.79 cw(c5179.39,4465.59) 5161.28,4465.59 ccw(c5179.39,4465.59) 5166.58,4452.79 ; 5166.58,4452.79 ccw(c5153.78,4439.98) 5153.78,4458.09 cw(c5153.78,4439.98) 5166.58,4452.79
  MidLayer1 w4: v1@4875.14,5273.43 ccw(c4858.92,5289.64) 4881.86,5289.64 ccw(c4904.79,5289.64) v1@4888.57,5273.43 ; v1@4877.97,5270.6 ccw(c4868.58,5279.99) 4881.86,5279.99 ccw(c4895.14,5279.99) v1@4885.75,5270.6 ; v1(4881.86,5266.71) 4881.86,5361.86 4940,5420 4940,5479.56 v1(4919.52,5500.04) ; v1@4919.52,5490.54 cw(c4919.52,5467.61) 4935.74,5483.82 cw(c4951.96,5500.04) v1@4929.02,5500.04 ; v1@4919.52,5494.54 cw(c4919.52,5481.26) 4928.91,5490.65 cw(c4938.3,5500.04) v1@4925.02,5500.04
  Bottom Layer w4: v1(4881.86,5266.71) 4918.29,5266.71 4925,5260 4925,5040 4893.04,5008.04 4526.84,5008.04 4468.17,5066.71 4265.19,5066.71 4240.19,5041.71 4240.19,4941.71 4256.86,4925.04 4723.52,4925.04 4759.55,4889.01 4781.06,4867.5 4964.4,4867.5 4990.19,4841.71 5106.86,4841.71 5115.19,4833.37 5115.19,4810 5051.27,4746.08 5051.27,4728.73 5051.27,4724.74 5051.27,4720 5051.27,4710 5051.27,4700.22 5051.27,4641.96 5051.27,4583.7 ccw(c5075.04,4583.7) 5075.04,4559.93 cw(c5075.04,4544.33) 5090.64,4544.33 ccw(c5114.41,4544.33) 5114.41,4520.56 cw(c5114.41,4504.96) 5130.01,4504.96 ccw(c5153.78,4504.96) 5136.97,4488.15 5143.39,4480.42 ; v1@4885.75,5262.82 cw(c4895.14,5253.43) 4895.14,5266.71 cw(c4895.14,5279.99) v1@4885.75,5270.6 ; v1@4888.57,5259.99 cw(c4904.79,5243.77) 4904.79,5266.71 cw(c4904.79,5289.64) v1@4888.57,5273.43 ; v1(4919.52,5500.04) U21.27@4977.68,5500.04 ; v1@4923.41,5496.15 cw(c4932.8,5486.76) 4932.8,5500.04 cw(c4932.8,5513.32) v1@4923.41,5503.93 ; v1@4926.24,5493.32 cw(c4942.46,5477.11) 4942.46,5500.04 cw(c4942.46,5522.98) v1@4926.24,5506.76 ; 4941.93,5500.04 ccw(c4941.93,5513.32) U21.27@4951.32,5503.93 ; 4947.06,5500.04 cw(c4947.06,5494.01) U21.27@4951.32,5498.27 ; v3@5146.39,4466.89 ccw(c5128.56,4470.04) 5143.39,4480.42 ; v3@5155.08,4472.98 cw(c5158.23,4490.81) 5143.39,4480.42
VGA.RED0: U8.A9 U21.15 | length 1174.7
  Top Layer w4: v4@5118.06,5453.06 cw(c5101.31,5436.31) 5125,5436.31 cw(c5148.69,5436.31) v4@5131.94,5453.06 ; v4@5120.89,5455.89 cw(c5110.97,5445.97) 5125,5445.97 cw(c5139.03,5445.97) v4@5129.11,5455.89 ; v4(5125,5460) 5125,5425.19 5140.19,5410 5140.19,5191.71 5198.52,5133.37 5205,5126.9 5205,5098.04 5209.7,5093.34 5209.7,5030 ; U8.A9@5207.53,4687.43 ccw(c5194.73,4700.23) 5212.83,4700.23 ccw(c5230.94,4700.23) U8.A9@5218.14,4687.43 ; U8.A9@5207.64,4687.32 ccw(c5195.11,4699.85) 5212.83,4699.85 ccw(c5230.56,4699.85) U8.A9@5218.03,4687.32 ; 5209.7,5050.79 5209.7,5030 ; U8.A9@5212.83,4682.13 5212.83,4710 5212.83,4720 5212.83,4819.7 5220.19,4827.06 5220.19,4879.04 5232.86,4891.71 5232.86,4957.37 5215.19,4975.04 5209.7,4980.53 5209.7,5030 ; 5212.84,4724.74 5212.84,4725.04
  Bottom Layer w4: v4(5125,5460) 5123.37,5458.37 5198.52,5458.37 5213.9,5443 U21.15@5213.9,5402.68 ; v4@5129.11,5464.11 ccw(c5142.95,5477.95) 5142.95,5458.37 ; v4@5131.94,5453.06 cw(c5144.76,5440.24) 5144.76,5458.37 ; v4@5131.94,5466.94 ccw(c5152.61,5487.61) 5152.61,5458.37 ; U21.15@5211.07,5429.03 ccw(c5204.24,5435.86) 5213.9,5435.86 ccw(c5223.55,5435.86) U21.15@5216.73,5429.03
VGA.RED1: U8.B9 U21.16 | length 1097.5
  Top Layer w4: 5198.52,4816.71 5202.62,4820.81 ; U8.B9@5205.49,4642.76 ccw(c5187.77,4642.76) 5200.3,4655.29 ; U8.B9@5212.83,4650.1 cw(c5212.83,4667.83) 5200.3,4655.29 ; v1(5215.19,4908.37) 5215.19,4894.71 5212.19,4891.71 5212.19,4830.37 ; 5200.3,4655.29 cw(c5207.48,4662.47) 5197.33,4662.47 5197.33,4710 5197.33,4720 5197.33,4724.74 5197.33,4815.51 5202.62,4820.81 ; 5202.62,4820.81 5212.19,4830.37 ; 5202.62,4820.81 5212.19,4830.37
  MidLayer1 w4: v1(5215.19,4908.37) 5240.19,4933.37 5240.19,4958.37 5264.7,4982.88 5264.7,5159.81 5256.86,5167.64 5256.86,5218.37 5290.19,5251.71 v1(5290.19,5275.04) ; v1@5215.19,4913.87 ccw(c5215.19,4927.15) 5224.58,4917.76 ccw(c5233.97,4908.37) v1@5220.69,4908.37 ; v1@5215.19,4917.87 ccw(c5215.19,4940.81) 5231.41,4924.59 ccw(c5247.63,4908.37) v1@5224.69,4908.37 ; v1@5283.47,5268.32 cw(c5267.26,5252.11) 5290.19,5252.11 cw(c5313.13,5252.11) v1@5296.91,5268.32 ; v1@5286.3,5271.15 cw(c5276.91,5261.76) 5290.19,5261.76 cw(c5303.47,5261.76) v1@5294.08,5271.15
  Bottom Layer w4: U21.16@5191.77,5375.98 cw(c5187.95,5371.02) 5194.21,5371.02 ; U21.16@5194.21,5402.68 5194.21,5371.02 ; U21.16@5196.65,5375.98 ccw(c5200.47,5371.02) 5194.21,5371.02 ; v1@5283.47,5268.32 ccw(c5267.26,5252.11) 5267.26,5275.04 ccw(c5267.26,5297.98) v1@5283.47,5281.76 ; v1@5286.3,5271.15 ccw(c5276.91,5261.76) 5276.91,5275.04 ccw(c5276.91,5288.32) v1@5286.3,5278.93 ; v1(5290.19,5275.04) 5229.96,5275.04 5194.21,5310.79 5194.21,5371.02
VGA.RED2: U8.D9 U21.17 | length 1194.3
  Top Layer w4: v3(5193.15,4583.7) U8.D9@5212.83,4564.02 ; U8.D9@5205.33,4564.02 ccw(c5187.23,4564.02) 5200.03,4576.82 ccw(c5212.83,4589.62) U8.D9@5212.83,4571.52 ; U8.D9@5205.49,4564.02 ccw(c5187.77,4564.02) 5200.3,4576.55 ccw(c5212.83,4589.08) U8.D9@5212.83,4571.36 ; 5205.95,4570.9 ccw(c5193.15,4558.09) 5193.15,4576.2 cw(c5193.15,4558.09) 5205.95,4570.9 ; 5205.95,4570.9 cw(c5218.76,4583.7) 5200.65,4583.7 ccw(c5218.76,4583.7) 5205.95,4570.9
  MidLayer1 w4: v3@5187.85,4589 ccw(c5175.04,4601.81) 5193.15,4601.81 ccw(c5211.26,4601.81) v3@5198.45,4589 ; v3@5187.96,4588.89 ccw(c5175.42,4601.43) 5193.15,4601.43 ccw(c5210.88,4601.43) v3@5198.34,4588.89 ; v3(5193.15,4583.7) 5193.15,4661.38 5193.15,4710 5193.15,4720 5193.15,4724.74 5193.15,4802.04 5165.19,4830 5165.19,4858.37 5181.86,4875.04 5181.86,5217.71 v1(5215.19,5251.04) ; v1@5205.69,5251.04 cw(c5182.76,5251.04) 5198.97,5234.82 cw(c5215.19,5218.61) v1@5215.19,5241.54 ; v1@5209.69,5251.04 cw(c5196.41,5251.04) 5205.8,5241.65 cw(c5215.19,5232.26) v1@5215.19,5245.54
  Bottom Layer w4: U21.17@5171.7,5376.32 cw(c5164.87,5369.49) 5174.53,5369.49 cw(c5184.18,5369.49) U21.17@5177.36,5376.32 ; U21.17@5174.53,5402.68 5174.53,5291.7 v1(5215.19,5251.04) ; v1@5205.69,5251.04 ccw(c5182.76,5251.04) 5198.97,5267.26 ccw(c5215.19,5283.48) v1@5215.19,5260.54 ; v1@5209.69,5251.04 ccw(c5196.41,5251.04) 5205.8,5260.43 ccw(c5215.19,5269.82) v1@5215.19,5256.54
VGA.RED3: U8.G9 U21.18 | length 1737.5
  Top Layer w4: v3(5193.15,4465.59) U8.G9@5212.83,4445.91 ; U8.G9@5205.33,4445.91 ccw(c5187.23,4445.91) 5200.03,4458.71 ccw(c5212.83,4471.51) U8.G9@5212.83,4453.41 ; U8.G9@5205.49,4445.91 ccw(c5187.77,4445.91) 5200.3,4458.44 ccw(c5212.83,4470.97) U8.G9@5212.83,4453.25 ; 5205.95,4452.79 ccw(c5193.15,4439.98) 5193.15,4458.09 cw(c5193.15,4439.98) 5205.95,4452.79 ; 5205.95,4452.79 cw(c5218.76,4465.59) 5200.65,4465.59 ccw(c5218.76,4465.59) 5205.95,4452.79
  MidLayer2 w4: v1(5085,5085) 5083.48,5085 5081.86,5083.37 5131.63,5083.37 5135,5080 5255,5080 5270,5065 5270,5030 5265,5025 5174.56,5025 5057.94,4908.37 5048.52,4908.37 5028.19,4888.04 5028.19,4823.12 5062.22,4789.1 5067.27,4784.04 5170.96,4784.04 5177.64,4777.36 5177.64,4720 5177.64,4710 5177.64,4582.64 5177.64,4489.1 ; v1@5088.89,5088.89 ccw(c5102.2,5102.2) 5102.2,5083.37 ; v1@5091.72,5078.28 cw(c5104.01,5065.99) 5104.01,5083.37 ; v1@5091.72,5091.72 ccw(c5111.86,5111.86) 5111.86,5083.37 ; 5177.64,4503.03 5177.64,4489.1 ; 5181.76,4479.17 cw(c5191.69,4489.1) 5177.64,4489.1 ; v3@5185.68,4466.24 ccw(c5167.64,4467.82) 5181.51,4479.46 ccw(c5195.38,4491.1) v3@5193.8,4473.06
  Bottom Layer w4: v1@5078.28,5091.72 ccw(c5062.06,5107.93) 5085,5107.93 ccw(c5107.93,5107.93) v1@5091.72,5091.72 ; v1@5081.11,5088.89 ccw(c5071.72,5098.28) 5085,5098.28 ccw(c5098.28,5098.28) v1@5088.89,5088.89 ; U21.18@5152.01,5376.32 cw(c5145.19,5369.49) 5154.84,5369.49 cw(c5164.5,5369.49) U21.18@5157.67,5376.32 ; U21.18@5154.84,5402.68 5154.84,5326.31 5165.19,5315.96 5165.19,5218.88 5085,5138.69 v1@5085,5086.52 ; v1@5083.48,5085 5081.86,5083.37 v1@5083.48,5085 ; v1@5083.48,5085 v1(5085,5085) v1@5085,5086.52 ; v1@5083.48,5085 5084.24,5085.76 v1@5085,5086.52
VGA.RED4: U8.A8 U21.19 | length 1130.1
  Top Layer w4: v1(5123.52,5064.37) 5117.52,5058.37 5117.52,4927.35 5128.5,4916.37 5164.48,4916.37 5181.86,4899 5181.86,4869.73 5165.96,4853.83 5165.96,4835.73 5173.47,4828.22 5173.47,4724.74 5173.46,4720 5173.46,4710 U8.A8@5173.46,4682.13 ; U8.A8@5168.16,4687.43 ccw(c5155.36,4700.23) 5173.46,4700.23 ccw(c5191.57,4700.23) U8.A8@5178.77,4687.43 ; U8.A8@5168.27,4687.32 ccw(c5155.74,4699.85) 5173.46,4699.85 ccw(c5191.19,4699.85) U8.A8@5178.66,4687.32
  Bottom Layer w4: v1@5114.02,5064.37 cw(c5091.09,5064.37) 5107.31,5048.16 cw(c5123.52,5031.94) v1@5123.52,5054.87 ; v1@5118.02,5064.37 cw(c5104.75,5064.37) 5114.14,5054.99 cw(c5123.52,5045.6) v1@5123.52,5058.87 ; v1(5123.52,5064.37) 5092.52,5033.37 5024.52,5033.37 5006.86,5051.04 5006.86,5071.86 5156.86,5221.86 5156.86,5312.98 5135.16,5334.68 U21.19@5135.16,5402.68 ; U21.19@5132.33,5376.32 cw(c5125.5,5369.49) 5135.16,5369.49 cw(c5144.81,5369.49) U21.19@5137.99,5376.32
VGA.RED5: U8.J9 U21.20 | length 1896.7
  Top Layer w4: v3(5193.15,4386.85) U8.J9@5212.83,4367.17 ; U8.J9@5205.33,4367.17 ccw(c5187.23,4367.17) 5200.03,4379.97 ccw(c5212.83,4392.77) U8.J9@5212.83,4374.67 ; U8.J9@5205.49,4367.17 ccw(c5187.77,4367.17) 5200.3,4379.7 ccw(c5212.83,4392.23) U8.J9@5212.83,4374.51 ; 5205.95,4374.05 ccw(c5193.15,4361.24) 5193.15,4379.35 cw(c5193.15,4361.24) 5205.95,4374.05 ; 5205.95,4374.05 cw(c5218.76,4386.85) 5200.65,4386.85 ccw(c5218.76,4386.85) 5205.95,4374.05
  MidLayer2 w4: v1@4900.14,4898.43 ccw(c4883.92,4914.64) 4906.86,4914.64 ccw(c4929.79,4914.64) v1@4913.57,4898.43 ; v1@4902.97,4895.6 ccw(c4893.58,4904.99) 4906.86,4904.99 ccw(c4920.14,4904.99) v1@4910.75,4895.6 ; v1(4906.86,4891.71) 4906.86,5108.37 4936.52,5138.04 v1(5040.19,5138.04) ; v1@5033.47,5131.32 ccw(c5017.26,5115.11) 5017.26,5138.04 ccw(c5017.26,5160.98) v1@5033.47,5144.76 ; v1@5036.3,5134.15 ccw(c5026.91,5124.76) 5026.91,5138.04 ccw(c5026.91,5151.32) v1@5036.3,5141.93
  Bottom Layer w4: v1@4906.86,4882.21 cw(c4906.87,4859.31) 4923.06,4875.5 ; v1@4906.86,4886.21 cw(c4906.87,4872.95) 4916.24,4882.32 cw(c4925.61,4891.7) v1@4912.36,4891.71 ; v1(4906.86,4891.71) 4923.06,4875.5 ; v1@4916.36,4891.7 ccw(c4939.26,4891.69) 4923.06,4875.5 ; v1(5040.19,5138.04) 5061.73,5138.04 ; v1@5044.25,5134.33 cw(c5052.66,5126.66) 5052.66,5138.04 cw(c5052.66,5149.42) v1@5044.25,5141.75 ; v1@5047.21,5131.64 cw(c5061.73,5118.38) 5061.73,5138.04 ; v1@5047.21,5144.45 ccw(c5061.73,5157.7) 5061.73,5138.04 ; U21.20@5112.64,5376.32 cw(c5105.82,5369.49) 5115.47,5369.49 cw(c5125.13,5369.49) U21.20@5118.3,5376.32 ; U21.20@5115.47,5402.68 5115.47,5343.05 5148.52,5310 5148.52,5224.84 5061.73,5138.04 ; v3@5185.76,4388.15 ccw(c5167.93,4391.3) 5182.76,4401.68 ; v3@5194.45,4394.24 cw(c5197.6,4412.07) 5182.76,4401.68 ; 4923.06,4875.5 5019.98,4875.5 5044.52,4900.04 5124.84,4900.04 5133.5,4908.71 5150.19,4908.71 5167.19,4891.71 5167.19,4844.04 5156.52,4833.37 5156.52,4775 5169.38,4762.14 5169.38,4720 5169.38,4710 5169.38,4700.22 5169.38,4641.96 5169.38,4426.22 ccw(c5193.15,4426.22) 5176.34,4409.41 5182.76,4401.68
VGA.RED6: U8.H9 U21.21 | length 1821.4
  Top Layer w4: v3(5193.15,4426.22) U8.H9@5212.83,4406.54 ; U8.H9@5205.33,4406.54 ccw(c5187.23,4406.54) 5200.03,4419.34 ccw(c5212.83,4432.14) U8.H9@5212.83,4414.04 ; U8.H9@5205.49,4406.54 ccw(c5187.77,4406.54) 5200.3,4419.07 ccw(c5212.83,4431.6) U8.H9@5212.83,4413.88 ; 5205.95,4413.42 ccw(c5193.15,4400.61) 5193.15,4418.72 cw(c5193.15,4400.61) 5205.95,4413.42 ; 5205.95,4413.42 cw(c5218.76,4426.22) 5200.65,4426.22 ccw(c5218.76,4426.22) 5205.95,4413.42
  MidLayer1 w4: 5008.37,5020.53 ccw(c5035,5047.17) v1@5035,5009.5 ; 5015.19,5013.7 ccw(c5035,5033.51) v1@5035,5005.5 ; 5022.02,5006.88 ccw(c5035,5019.85) v1@5035,5001.5 ; 5023.1,5005.8 cw(c5017.3,5000) v1@5025.5,5000 ; v1(5035,5000) 5031.82,5000 v1@5030.36,4998.54 ; v1@5105.69,5300.04 ccw(c5082.76,5300.04) 5098.97,5316.26 ccw(c5115.19,5332.48) v1@5115.19,5309.54 ; v1@5109.69,5300.04 ccw(c5096.41,5300.04) 5105.8,5309.43 ccw(c5115.19,5318.82) v1@5115.19,5305.54 ; v1(5115.19,5300.04) 5056.86,5358.37 4990.19,5358.37 4973.52,5341.71 4973.52,5055.37 v1@5030.36,4998.54 ; v1@5030.36,4998.54 5030.86,4998.04 5029.86,4998.04 v1@5030.36,4998.54
  MidLayer2 w4: v1@5028.28,4993.28 cw(c5012.06,4977.06) 5035,4977.06 cw(c5057.93,4977.06) v1@5041.72,4993.28 ; v1@5031.11,4996.11 cw(c5021.72,4986.72) 5035,4986.72 cw(c5048.28,4986.72) v1@5038.89,4996.11 ; v1(5035,5000) 5035,4910 5020,4895 5020,4820 5063.96,4776.04 5167.65,4776.04 5169.29,4774.4 5169.29,4720 5169.29,4710 5169.29,4640.9 ; 5169.29,4699.16 5169.29,4640.9 ; v3@5185.76,4427.52 ccw(c5167.93,4430.67) 5182.76,4441.05 ; v3@5194.45,4433.61 cw(c5197.6,4451.44) 5182.76,4441.05 ; 5169.29,4640.9 5169.29,4582.64 5169.29,4563.22 5169.29,4489.1 5169.29,4465.85 ccw(c5193.06,4465.85) 5175.68,4449.63 5182.76,4441.05
  Bottom Layer w4: U21.21@5092.96,5376.32 cw(c5086.13,5369.49) 5095.79,5369.49 cw(c5105.44,5369.49) U21.21@5098.62,5376.32 ; U21.21@5095.79,5402.68 5095.79,5362.74 5098.52,5360 5098.52,5325.04 5115.19,5308.37 v1(5115.19,5300.04) ; 5100.85,5322.71 cw(c5079.47,5301.32) v1@5109.69,5300.24 ; 5107.35,5316.21 cw(c5092.01,5300.87) v1@5113.69,5300.09
VGA.RED7: U8.B8 U21.22 | length 1025.3
  Top Layer w4: v1(5098.52,5008.37) 5109.52,4997.37 5109.52,4924.04 5125.19,4908.37 5159.19,4908.37 5173.52,4894.04 5173.52,4872.71 5157.96,4857.14 5157.96,4724.74 5157.96,4720 5157.96,4710 5157.96,4662.47 ccw(c5168.11,4662.47) 5160.93,4655.29 ; U8.B8@5166.12,4642.76 ccw(c5148.4,4642.76) 5160.93,4655.29 ; U8.B8@5173.46,4650.1 cw(c5173.46,4667.83) 5160.93,4655.29
  Bottom Layer w4: U21.22@5073.27,5376.32 cw(c5066.45,5369.49) 5076.1,5369.49 cw(c5085.76,5369.49) U21.22@5078.93,5376.32 ; U21.22@5076.1,5402.68 5076.1,5358.37 5062.52,5344.8 5062.52,5300.08 5065.36,5297.25 5065.36,5210.21 4998.52,5143.37 4998.52,5033.37 5011.9,5020 5060,5020 5062.5,5017.5 5071.63,5008.37 v1(5098.52,5008.37) ; v1@5091.81,5001.66 ccw(c5075.59,4985.44) 5075.59,5008.37 ccw(c5075.59,5031.31) v1@5091.81,5015.09 ; v1@5094.64,5004.49 ccw(c5085.25,4995.1) 5085.25,5008.37 ccw(c5085.25,5021.65) v1@5094.64,5012.26
VGA.VGA_CLK: U8.C5 U21.26 | length 1338.5
  Top Layer w4: v1@4887.19,5493.54 cw(c4887.19,5470.61) 4903.41,5486.82 cw(c4919.63,5503.04) v1@4896.69,5503.04 ; v1@4887.19,5497.54 cw(c4887.19,5484.26) 4896.58,5493.65 cw(c4905.97,5503.04) v1@4892.69,5503.04 ; v1(4887.19,5503.04) 4915.19,5475.04 4920.52,5475.04 4928.86,5466.71 4928.86,5440 4930,5440 4960.25,5409.75 4970,5400 4970,5303.56 4973.86,5299.71 4981.86,5291.71 4981.86,5200.04 4915.19,5133.37 4915.19,4959.71 5012.81,4862.09 ; 5023.52,4851.37 5012.81,4862.09 ; 5012.81,4862.09 5031.49,4843.41 5031.49,4720 5031.49,4710 5031.49,4643.27 ; 5031.49,4643.27 ccw(c5070.17,4643.27) 5042.82,4615.92 ; 5031.49,4643.27 ccw(c5070.17,4643.27) 5042.82,4615.92 ; 5042.82,4615.92 cw(c5030.29,4603.39) 5048.01,4603.39 ccw(c5030.29,4603.39) 5042.82,4615.92 ; 5042.82,4615.92 ccw(c5055.35,4628.45) 5055.35,4610.73 cw(c5055.35,4628.45) 5042.82,4615.92
  Bottom Layer w4: v1@4887.19,5493.54 cw(c4887.19,5470.61) 4903.41,5486.82 cw(c4919.63,5503.04) v1@4896.69,5503.04 ; v1@4887.19,5497.54 cw(c4887.19,5484.26) 4896.58,5493.65 cw(c4905.97,5503.04) v1@4892.69,5503.04 ; v1(4887.19,5503.04) 4907.69,5482.54 4976.55,5482.54 U21.26@4977.68,5481.42 ; 4941.78,5482.54 cw(c4941.78,5469.05) U21.26@4951.32,5478.59 ; 4947.21,5482.54 ccw(c4947.21,5488.36) U21.26@4951.32,5484.25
